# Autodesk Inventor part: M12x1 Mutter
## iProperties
Shininess: 64.0
Length Units: 11269
Angle Units: 11279
Time Units: 11290
Mass Units: 11283
Length Display Precision: 3
Angle Display Precision: 2
Compacted: True
Part Number: M12x1 Mutter
Document SubType Name: Modeling
Created: 2003-04
Material: Standard
Designer: li
Density: 0.0
Volumn: 0.0
Area: 0.0
PropertySet Name: Model Information
Control State: 0
Master: False
Checked Out: False
Author: li
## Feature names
1. Extrusion1
2. Fase1 [Chamfer]
3. Fase2 [Chamfer]
4. Extrusion2
5. Fase3 [Chamfer]
6. Fase4 [Chamfer]
7. Extrusion3
